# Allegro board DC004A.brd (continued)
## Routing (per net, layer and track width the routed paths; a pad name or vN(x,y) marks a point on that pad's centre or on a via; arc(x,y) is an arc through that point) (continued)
VBUS:
  vias: v1(32.95,36.48)
VBUSS: length 1.9
  BOTTOM w0.305: v1(31.05,39.98) 31.05,39.05 31.34,38.76 C173.1
VCCIN: length 2.3
  TOP w0.381: v1(66.02,137.01) 65.88,137.15 C104.2
  BOTTOM w0.305: v1(66.02,137.01) 65.92,137.11 U3.10
VDDD33: length 28.5
  TOP w0.254: U11.7 v1(76.22,58.61) ; U2.1 v1(12.15,124.12) ; U11.8 v1(76.2,57.96) ; U2.10 11.25,123.75 v1(11.68,123.32) ; U11.16 U11.1 77.62,62.5 v1(77.62,62.14) 77.61,62.13 U11.2
  TOP w0.305: U8.42 v1(64.76,62.35) ; v1(62.31,55.96) U8.31 ; U8.20 v1(56.8,56.1) ; U8.56 v1(59.31,67.09) ; U12.16 87.62,72.27 v1(87.62,73.15)
  TOP w0.356: U10.8 v1(44.69,35.44) ; U10.2 43.58,39.75 v1(43.59,39.75) 43.59,39.99 U10.1 ; U10.16 v1(49.23,40.47)
  TOP w0.508: v1(74.36,68.98) v1(74.36,67.84)
  BOTTOM w0.279: C190.1 v1(48.67,53.11)
  BOTTOM w0.305: v1(56.8,56.1) C186.1 ; C188.1 v1(62.31,55.96) ; C187.1 63.31,62.35 v1(64.76,62.35) ; C189.1 59.31,67.09 v1(59.31,67.09)
  BOTTOM w0.508: C180.1 76.95,73.12 v1(77.02,73.19) ; FB12.1 51.82,66.29 v1(52.2,66.67)
  vias: v1(6.68,125.64) v1(6.68,124.5) v1(6.68,123.35) v1(11.68,122.17) v1(14.48,127.25) v1(24.51,145.67) v1(24.51,144.65) v1(24.51,143.64) v1(24.51,142.75) v1(24.51,141.73) v1(25.27,143.76) v1(25.27,141.61) v1(25.78,145.03) v1(26.01,143) v1(26.16,141.61) v1(26.29,143.89) v1(42.04,120.78) v1(42.14,124.76) v1(42.65,125.26) v1(42.65,124.25) v1(42.8,121.28) v1(43.43,120.78) v1(50.55,70.61) v1(50.98,58.84) v1(51.31,69.85) v1(51.38,60.07) v1(66.88,53.78) v1(68.96,63.75) v1(68.96,61.47) v1(78.82,65.6) v1(107.95,68.83) v1(107.98,66.17) v1(107.98,64.52) v1(107.98,62.61) v1(110.24,62.23)
VDDL19: length 8.7
  TOP w0.305: U12.15 87.57,71.62 v1(85.86,71.62) ; U11.15 v1(81.75,61.86)
  BOTTOM w0.279: v1(47.52,39.24) 47.62,39.34 v1(49.23,39.34) 49.13,39.24 R132.1
  BOTTOM w0.508: v1(81.75,61.86) 81.78,61.89 C193.1 ; C195.1 v1(85.86,71.62)
  vias: v1(72.97,70.3) v1(73.05,69.52) v1(73.66,70.65) v1(73.77,69.86) v1(83.85,40.77) v1(84.71,41.53) v1(85.22,40.77) v1(85.34,39.37) v1(85.85,41.53) v1(86.36,39.62) v1(86.49,38.73) v1(86.74,41.53) v1(86.74,40.26) v1(87.5,41.53)
VINA: length 4.8
  TOP w0.279: BALUN1.1 31.93,123.44
VINB: length 4.8
  TOP w0.279: BALUN2.1 31.93,68.07
1P8V_USB: length 51.7
  TOP w0.305: U8.64 v1(55.3,66.99) ; v1(64.67,59.84) U8.37 ; v1(63.12,68.07) 62.81,67.76 U8.49 ; v1(53.8,59.84) U8.12
  L10_SIG-2 w0.508: 56.11,58.85 53.14,55.88 v1(44.07,55.88)
  BOTTOM w0.254: v1(55.3,66.99) 55.3,66.05 C181.1
  BOTTOM w0.279: 54.61,57.15 54.61,59.46 C182.1 54.05,59.59 v1(53.8,59.84) ; C183.1 v1(64.67,59.84) 65.03,59.48
  BOTTOM w0.305: v1(63.12,68.07) 62.81,67.76 C179.1
  BOTTOM w0.508: v1(44.07,55.88) 53.34,55.88 54.61,57.15 56.77,54.99 63.32,54.99 65.41,57.08 65.41,59.1 65.03,59.48
  vias: v1(62.74,68.58) v1(63.5,67.56)
3P3USB: length 16.9
  TOP w0.305: U8.9 53.95,61.34 53.94,61.36 53.51,61.36 52.65,60.5 v1(52.65,60.07)
  BOTTOM w0.254: v1(44.07,59.69) 46.07,59.69 47.11,60.73 50.47,60.73 51.71,61.98 53.72,61.98 54.36,61.34 53.95,61.34 53.91,61.38 53.31,61.38 C171.1
  BOTTOM w0.279: C171.1 53.26,61.24 53.16,61.14 53.16,60.99 53.15,60.97 53.15,60.57 v1(52.65,60.07)
  BOTTOM w0.508: C170.1 54.36,61.34
3P3V_RX: length 19.5
  BOTTOM w0.279: v1(139.06,58.93) 139.06,58.63 137.58,57.15 125.98,57.15 123.95,55.12 v1(121.28,55.12)
3P3VAUX: length 29.7
  TOP w0.279: v1(122.73,58.93) 121.78,58.93 121.61,59.09 U5.8
  L04_SIG-1 w0.165: J28.4 123.19,62.48 123.83,61.85 123.83,60.02 v1(122.73,58.93)
  BOTTOM w0.102: 128.52,70.87 138.43,70.87 J25.D32
  BOTTOM w0.279: J28.4 124.59,70.87 128.52,70.87
12P0V_RX:
  vias: v1(140.34,67.69) v1(140.34,65.15)
ADBUS0: length 6.3
  TOP w0.152: SJP3.3 50.93,55.75 53.02,57.84 53.4,57.84 53.4,57.84 53.78,57.84 53.79,57.84 U8.16
ADBUS1: length 5.2
  TOP w0.152: SJP4.3 52.58,55.88 53.71,57.02 U8.17
ADBUS2: length 3.8
  TOP w0.152: SJP5.3 54.23,54.74 55.8,56.31 U8.18
ADBUS3: length 3.3
  TOP w0.152: U8.19 56.3,54.14 SJP6.3
ADC_CLK: length 90.3
  L04_SIG-1 w0.14: 43.88,67.73 43.88,61.09 38.73,55.94 38.73,43.69 v1(38.86,43.56) 41.4,41.02 44.07,41.02 45.09,40 v1(53.34,40)
  L04_SIG-1 w0.152: v1(41.42,96.26) 43.57,96.26 44.98,94.84 44.98,89.18 45.34,88.82 45.34,79.38 43.88,77.92 43.88,67.73
  BOTTOM w0.127: v1(53.34,40) 51.63,41.72 40.83,41.72 38.99,43.56 v1(38.86,43.56)
ADC_SCSB: length 97.7
  L04_SIG-1 w0.089: 34.93,88.39 34.93,90.47 35.23,90.78 35.69,90.78 35.94,91.03 35.94,95.66 36.07,95.78 39.95,95.78 v1(40.43,96.26)
  L04_SIG-1 w0.14: v1(53.34,36.58) 51.94,36.58 51.35,37.17 38.9,37.17 35.46,40.61 35.46,62.13 35.71,62.38 35.71,76.34 35.17,76.88 35.17,83.19 34.29,84.07 34.29,87.76 34.93,88.39
  BOTTOM w0.127: v1(53.34,36.58) 53.34,35.18 52.32,34.16 40.01,34.16 v1(38.86,35.31)
ADC_SDI: length 98.4
  L04_SIG-1 w0.14: v1(53.34,38.86) 53.09,38.61 46.48,38.61 46.2,38.89 46.12,38.82 45.77,38.82 45.6,38.99 39.88,38.99 36.37,42.49 36.37,76.58
  L04_SIG-1 w0.152: 36.37,76.58 35.81,77.14 35.81,86.66 36.22,87.07 42.29,87.07 44.2,88.98 44.2,95 43.46,95.73 40.9,95.73 v1(40.43,95.26)
  BOTTOM w0.127: v1(53.34,38.86) 52.32,38.86 50.04,41.15 48.9,41.15 48.51,40.77 v1(38.86,40.77)
ADC_SDO: length 96.2
  L04_SIG-1 w0.089: v1(41.42,95.26) 41.42,94.03 41.22,93.83 37.13,93.83 36.91,93.6 36.91,88.85 36.45,88.39
  L04_SIG-1 w0.14: v1(53.34,37.72) 40.13,37.72 36.02,41.83 36.02,62.24 36.03,62.25 36.03,76.47 35.49,77.01 35.49,87.43 36.45,88.39
  BOTTOM w0.127: v1(38.86,38.1) 38.86,37.47 41.78,34.54 51.94,34.54 52.45,35.05 52.45,36.83 v1(53.34,37.72)
BDBUS0: length 2.9
  TOP w0.279: R112.1 59.82,55.79 59.79,55.82 59.79,56.25 59.82,56.28 59.82,57 U8.26
BDBUS1: length 6.4
  TOP w0.279: v1(60.31,56.03) U8.27 ; U7.2 v1(63.13,52.83)
  L10_SIG-2 w0.165: v1(60.31,56.03) 60.31,55.65 v1(63.13,52.83)
BDBUS2: length 3
  TOP w0.279: U8.28 60.81,56.27 60.83,56.25 60.83,55.82 60.81,55.8 60.81,54.26 R113.1
BDBUS3: length 5.2
  TOP w0.279: U8.29 61.31,55.41 62.93,53.78 U7.1
CALTRG: length 33.9
  TOP w0.152: v1(36.2,104.65) 36.2,103.76 36.43,103.53 U1.A9
  L04_SIG-1 w0.14: 39.12,124.21 39.37,124.21 40.77,122.81 44.32,122.81 44.7,122.43 44.7,109.86 41.15,106.3 37.56,106.3 36.92,105.66
  L04_SIG-1 w0.152: 36.92,105.66 36.2,104.93 v1(36.2,104.65)
  BOTTOM w0.254: 37.47,124.21 39.12,124.21
CDBUS0: length 4.8
  TOP w0.279: R118.1 66.78,60.34 64.91,60.34 64.89,60.36 64.45,60.36 64.43,60.34 U8.38
CDBUS1: length 4.5
  TOP w0.279: R119.1 67.43,60.84 U8.39
CDBUS2: length 6.9
  TOP w0.279: R120.1 69.34,62.1 68.58,62.1 R115.2 67.82,61.34 U8.40
CDBUS3: length 7.8
  TOP w0.254: R114.2 67.94,62.99 68.33,62.61 R121.1
  TOP w0.279: 67.94,62.99 66.8,61.85 64.99,61.85 64.97,61.82 64.54,61.82 64.52,61.85 U8.41
CE: length 5.3
  BOTTOM w0.279: U3.1 66.97,141.61 R46.1 67.79,142.44 68.81,142.44 JP5.2
CLK+: length 3.3
  TOP w0.279: C49.1 21.72,96.27 20.7,96.27 20.12,96.85 arc(19.92,96.98) 19.68,97.03 T2.1
CLK-: length 3.3
  TOP w0.279: T2.3 19.68,94.49 arc(19.92,94.53) 20.12,94.67 R43.1 21.72,95.25 C52.1
CLK-IN: length 5.7
  BOTTOM w0.279: R70.2 R72.1 R67.1 T1.6 R69.1
CLK_+: length 5.6
  TOP w0.279: U1.G1 23.17,96.26 arc(23,96.29) v1(22.86,96.39)
CLK_-: length 5.6
  TOP w0.279: U1.H1 23.17,95.26 arc(23,95.23) v1(22.86,95.13)
CLKIN0: length 27.9
  BOTTOM w0.279: J38.1 84.43,124.91 arc(85.14,124.77) 85.73,124.37 85.96,124.15 arc(86.1,124.06) 86.26,124.02 R187.1 87.81,124.02 R186.1
CLKIN0_N: length 3.9
  BOTTOM w0.254: C24.2 90.05,124.53 arc(90.26,124.49) 90.45,124.37 arc(91.09,123.94) 91.84,123.79 U4.38
CLKIN0_P: length 3.8
  BOTTOM w0.254: C20.2 90.28,123.77 arc(90.38,123.75) 90.46,123.69 90.58,123.57 arc(90.89,123.37) 91.24,123.3 92.96,123.3 92.97,123.29 U4.37
CLKIN1: length 0.7
  BOTTOM w0.279: R186.2 C20.1
CLKIN1_N: length 4
  BOTTOM w0.254: C136.2 90.52,122.42 C137.2 arc(90.77,122.36) 90.97,122.23 91.04,122.16 arc(91.18,122.06) 91.35,122.03 92.23,122.03 arc(92.38,122.06) 92.51,122.14 arc(92.66,122.25) 92.85,122.29 U4.35
CLKIN1_P: length 4
  BOTTOM w0.254: U4.34 93.17,121.79 arc(92.99,121.75) 92.84,121.65 92.76,121.57 arc(92.48,121.38) 92.14,121.32 91.18,121.32 arc(90.9,121.37) 90.66,121.53 arc(90.52,121.63) 90.35,121.66 C134.2
CLKINN: length 4.4
  BOTTOM w0.279: C136.1 87.43,122.42 R73.2 86.8,123.05 arc(86.57,123.21) 86.29,123.26 T1.3
CLKINP: length 5.1
  BOTTOM w0.279: C134.1 R68.1 87.53,121.66 R73.1 86.84,120.97 arc(86.56,120.79) 86.23,120.72 T1.1 R69.2
CLKLA_0N: length 5.1
  BOTTOM w0.152: U4.63 101.27,130.11 101.16,130.22 101.16,133.53 R90.1 101.35,134.39 R127.1
CLKLA_0P: length 5.1
  BOTTOM w0.152: U4.62 100.77,130.14 100.88,130.25 100.88,133.53 R89.1 100.69,134.39 R126.1
CLKM: length 105.3
  BOTTOM w0.254: C135.2 104.3,116.41 104.3,114.87 arc(103.45,112.81) 101.39,111.96 37.32,111.96 arc(36.49,112.13) 35.79,112.6 34.93,113.46 arc(34.46,113.76) 33.91,113.87 30.91,113.87 arc(30.68,113.91) 30.48,114.05 30.47,114.06 arc(30.41,114.11) 30.35,114.16 arc(30.14,114.25) 29.93,114.28 29.81,114.28 arc(29.48,114.22) 29.19,114.02 arc(29.02,113.91) 28.83,113.86 arc(27.53,113.55) 26.43,112.79 25.78,112.14 arc(25.61,112.02) 25.41,111.98 arc(25.2,111.9) 25.02,111.76 arc(24.93,111.62) 24.89,111.45 arc(24.85,111.27) 24.75,111.11 24.21,110.57 arc(23.91,110.37) 23.56,110.3 arc(23.15,110.13) 22.99,109.73 arc(22.96,109.61) 22.9,109.51 22.7,109.32 arc(22.54,109.07) 22.48,108.78 22.48,108.42 arc(22.46,108.18) 22.4,107.93 arc(22.2,107.11) 22.13,106.26 arc(22.15,106.19) 22.15,106.13 22.15,105.79 arc(22.11,105.54) 22.01,105.32 21.97,105.28 arc(21.81,105.03) 21.75,104.73 arc(21.78,104.4) 21.89,104.09 21.89,104.09 arc(22.08,103.8) 22.15,103.46 22.15,102.98 arc(22.11,102.76) 21.98,102.57 21.98,102.57 arc(21.8,102.2) 21.74,101.78 arc(21.79,101.51) 21.95,101.28 arc(22.1,101.05) 22.15,100.79 22.15,100.46 arc(22.65,99.24) 23.88,98.73 24.77,98.73 arc(25.34,98.49) 25.58,97.92 25.58,96.65 arc(25.42,96.27) 25.04,96.11 24.72,96.11 arc(24.62,96.13) 24.54,96.19 24.41,96.32 arc(24.33,96.37) 24.23,96.39 C48.1
CLKP: length 105.2
  BOTTOM w0.254: C133.2 105.01,116.41 105.01,114.87 arc(103.95,112.31) 101.39,111.25 37.32,111.25 arc(36.22,111.47) 35.29,112.09 34.44,112.94 arc(34.19,113.1) 33.91,113.16 29.03,113.16 arc(28.95,113.15) 28.87,113.15 arc(27.82,112.9) 26.93,112.28 26.02,111.37 24.34,109.69 arc(23.24,108.06) 22.86,106.13 22.86,100.46 arc(23.16,99.74) 23.88,99.44 24.77,99.44 arc(25.84,98.99) 26.29,97.92 26.29,96.65 arc(25.92,95.77) 25.04,95.4 24.72,95.4 arc(24.62,95.38) 24.54,95.33 24.41,95.2 arc(24.33,95.14) 24.23,95.12 C53.1
CP1: length 38.7
  L04_SIG-1 w0.14: v1(94.21,118.43) 89.41,118.43 85.55,122.3 85.55,128.87 77.07,137.36 v1(77.07,141.29)
  BOTTOM w0.279: v1(77.07,141.29) 77.07,144.9 C130.1 ; v1(94.21,118.43) 94.27,118.49 U4.32
CP2: length 4.9
  BOTTOM w0.127: 90.11,128.98 C131.1 ; U4.46 93.44,127.79
  BOTTOM w0.279: 93.44,127.79 92.38,127.79 91.19,128.98 90.11,128.98 ; C132.1 C131.1
CPOUT: length 17.7
  TOP w0.279: v1(64.14,134.37) 67.06,134.37 68.07,135.38 68.07,139.83 67.31,140.59 67.31,144.06 v1(67.69,144.44)
  BOTTOM w0.127: v1(64.14,134.37) 64.11,134.39 64.11,135.26 63.8,135.56
  BOTTOM w0.203: 63.8,135.56 U3.12
  BOTTOM w0.254: C120.1 C119.1 v1(67.69,144.44)
DA0+: length 1.5
  TOP w0.254: C5.1 41.77,98.11 arc(41.58,98.15) U1.E14
DA0-: length 1.5
  TOP w0.254: C6.1 41.77,97.4 arc(41.58,97.37) U1.F14
DA0_M: length 100.6
  TOP w0.254: C6.2 43.97,97.4 115.67,97.4 arc(116.12,97.31) 116.51,97.05 116.68,96.88 arc(117.39,96.41) 118.23,96.24 124.08,96.24 v1(124.12,96.2)
  BOTTOM w0.254: J25.A11 142.58,97.88 arc(142.2,97.62) 141.76,97.54 128.55,97.54 arc(128.46,97.56) 128.37,97.61 128.24,97.74 arc(128.16,97.8) 128.06,97.82 127.66,97.82 arc(127.38,97.76) 127.13,97.59 126.37,96.83 arc(125.7,96.38) 124.91,96.23 124.14,96.23 v1(124.12,96.2)
DA0_P: length 100.6
  TOP w0.254: C5.2 115.67,98.11 arc(116.4,97.97) 117.01,97.56 117.18,97.39 arc(117.67,97.06) 118.23,96.95 124.1,96.95 v1(124.12,96.96)
  BOTTOM w0.254: v1(124.12,96.96) 124.14,96.94 124.91,96.94 arc(125.43,97.04) 125.87,97.33 126.63,98.1 arc(127.1,98.42) 127.66,98.53 128.06,98.53 arc(128.16,98.55) 128.24,98.6 128.37,98.73 arc(128.46,98.79) 128.55,98.81 141.84,98.81 arc(142.21,98.88) 142.52,99.09 J25.A10
DA1+: length 1.5
  TOP w0.254: C7.1 41.77,100.11 arc(41.58,100.15) U1.C14
DA1-: length 1.5
  TOP w0.254: C8.1 41.77,99.4 arc(41.58,99.37) U1.D14
DA1_M: length 99.6
  TOP w0.254: v1(118.56,100.94) 118.53,100.94 118.11,100.52 arc(117.61,100.19) 117.03,100.08 46.32,100.08 arc(46.02,100.02) 45.77,99.85 arc(45.28,99.52) 44.7,99.4 43.97,99.4 C8.2
  BOTTOM w0.254: v1(118.56,100.94) 118.56,100.98 120.43,102.85 arc(121.19,103.36) 122.08,103.53 122.65,103.53 arc(122.83,103.5) 122.98,103.4 123.46,102.92 arc(123.6,102.83) 123.76,102.79 123.88,102.79 arc(124.04,102.83) 124.18,102.92 124.67,103.41 arc(124.81,103.5) 124.97,103.53 127.02,103.53 arc(127.38,103.46) 127.69,103.25 128.09,102.85 arc(128.36,102.68) 128.67,102.61 129.02,102.61 138.99,102.62 139.88,102.62 arc(140.2,102.75) 140.34,103.07 J25.C7
DA1_P: length 99.6
  TOP w0.254: C7.2 44.7,100.11 arc(45.01,100.17) 45.27,100.35 45.27,100.35 arc(45.75,100.67) 46.32,100.79 112.8,100.79 arc(113.02,100.83) 113.2,100.95 113.62,101.37 arc(113.84,101.52) 114.1,101.57 114.29,101.57 arc(114.56,101.52) 114.78,101.37 115.09,101.06 115.22,100.93 arc(115.38,100.83) 115.57,100.79 117.03,100.79 arc(117.34,100.85) 117.6,101.03 118.02,101.45 v1(118.02,101.48)
  BOTTOM w0.254: J25.C6 140.34,104.7 arc(140.2,105.02) 139.88,105.16 138.99,105.16 129.02,105.16 128.67,105.16 arc(128.35,105.1) 128.08,104.92 127.69,104.52 arc(127.38,104.32) 127.02,104.24 122.08,104.24 arc(120.92,104.01) 119.93,103.35 118.06,101.48 v1(118.02,101.48)
DA2+: length 1.5
  TOP w0.254: C9.1 39.57,102.61 arc(39.53,102.42) U1.A12
DA2-: length 1.5
  TOP w0.254: C10.1 40.28,102.61 arc(40.32,102.42) U1.A13
DA2_M: length 108.2
  TOP w0.254: C10.2 40.28,104.37 arc(40.6,105.15) 41.38,105.47 42.22,105.47 arc(42.41,105.43) 42.57,105.32 42.7,105.19 42.84,105.06 arc(43.02,104.93) 43.23,104.89 43.4,104.89 arc(43.64,104.94) 43.85,105.08 43.96,105.19 44.09,105.32 arc(44.25,105.43) 44.45,105.47 45.17,105.47 arc(45.37,105.43) 45.53,105.32 45.66,105.19 45.8,105.06 arc(46.01,104.91) 46.27,104.86 arc(46.56,104.92) 46.81,105.08 46.92,105.19 47.05,105.32 arc(47.21,105.43) 47.41,105.47 48.24,105.47 arc(48.43,105.43) 48.6,105.32 48.72,105.19 48.86,105.06 arc(49.04,104.93) 49.26,104.89 49.42,104.89 arc(49.66,104.94) 49.87,105.08 49.99,105.19 50.11,105.32 arc(50.28,105.43) 50.47,105.47 108.75,105.47 arc(109.98,105.71) 111.02,106.41 arc(111.5,106.73) 112.06,106.84 136.2,106.84 arc(136.67,106.64) 136.86,106.17 136.86,104.28 arc(137.27,103.3) 138.26,102.89 140.97,102.89 arc(141.1,102.86) 141.21,102.79 arc(141.36,102.69) 141.53,102.66 142.28,102.66 arc(142.7,102.83) v1(142.88,103.25)
DA2_P: length 108.2
  TOP w0.254: C9.2 39.57,104.37 arc(40.1,105.65) 41.38,106.18 108.75,106.18 arc(109.71,106.37) 110.52,106.91 arc(111.22,107.38) 112.05,107.55 136.2,107.55 arc(137.17,107.15) 137.57,106.17 137.57,104.28 arc(137.77,103.8) 138.26,103.6 140.72,103.6 arc(140.95,103.65) 141.15,103.78 141.16,103.79 arc(141.29,103.87) 141.45,103.91 142.26,103.91 arc(142.69,104.09) v1(142.88,104.52)
DA3+: length 1.5
  TOP w0.254: C11.1 37.57,102.61 arc(37.53,102.42) U1.A10
DA3-: length 1.5
  TOP w0.254: C12.1 38.28,102.61 arc(38.32,102.42) U1.A11
DA3_M: length 108.3
  TOP w0.254: C12.2 38.28,105.03 arc(38.34,105.32) 38.51,105.57 39.73,106.79 arc(41.49,107.97) 43.56,108.38 44.32,108.38 arc(44.63,108.32) 44.89,108.15 44.97,108.06 arc(45.13,107.96) 45.31,107.92 45.82,107.92 arc(46.03,107.96) 46.21,108.08 46.34,108.21 arc(46.5,108.32) 46.7,108.36 47.17,108.36 arc(47.36,108.32) 47.53,108.21 47.65,108.09 47.79,107.95 arc(47.94,107.85) 48.13,107.81 48.41,107.81 arc(48.62,107.85) 48.8,107.97 48.92,108.08 49.04,108.21 arc(49.21,108.32) 49.4,108.36 50.96,108.36 arc(51.24,108.31) 51.47,108.15 51.48,108.14 arc(51.79,107.93) 52.16,107.86 arc(52.5,107.93) 52.79,108.12 arc(53.03,108.29) 53.33,108.35 53.74,108.35 arc(53.94,108.3) 54.12,108.19 54.12,108.18 arc(54.38,108.01) 54.68,107.95 arc(54.85,107.98) 54.99,108.08 arc(55.31,108.29) 55.68,108.36 106.65,108.36 v1(106.68,108.34)
  BOTTOM w0.254: v1(106.68,108.34) 106.7,108.36 113.79,108.36 arc(114.45,108.49) 115.01,108.86 arc(115.43,109.15) 115.93,109.25 128.06,109.25 arc(128.16,109.23) 128.24,109.17 128.37,109.04 arc(128.46,108.99) 128.55,108.97 141.76,108.97 arc(142.2,108.88) 142.58,108.62 J25.A3
DA3_P: length 108.2
  TOP w0.254: v1(106.68,109.1) 43.95,109.1 43.95,109.09 43.56,109.09 arc(41.21,108.63) 39.22,107.3 38,106.07 arc(37.68,105.59) 37.57,105.03 C11.2
  BOTTOM w0.254: v1(106.68,109.1) 106.7,109.07 113.79,109.07 arc(114.18,109.15) 114.5,109.37 arc(115.16,109.8) 115.93,109.96 128.06,109.96 arc(128.16,109.98) 128.24,110.03 128.37,110.16 arc(128.46,110.22) 128.55,110.24 141.76,110.24 arc(142.2,110.15) 142.58,109.89 J25.A2
DA4+: length 1.5
  BOTTOM w0.254: C13.1 40.77,98.11 arc(40.58,98.15) v1(40.43,98.26)
DA4-: length 1.5
  BOTTOM w0.254: C15.1 40.77,97.4 arc(40.58,97.36) v1(40.43,97.26)
DA4_M: length 106.5
  L10_SIG-2 w0.16: v1(107.38,94.33) 107.45,94.33 107.98,93.8 arc(108.65,93.35) 109.45,93.19 115.79,93.19 arc(117.03,92.94) 118.08,92.24 arc(119.58,91.24) 121.35,90.89 136.59,90.89 arc(137.89,91.14) 138.98,91.88 139.03,91.92 arc(139.93,92.52) 140.99,92.73 141.1,92.73 arc(141.2,92.72) 141.3,92.69 arc(141.36,92.65) 141.41,92.61 arc(141.59,92.49) 141.79,92.45 144.95,92.45 arc(145.28,92.59) 145.41,92.92 v1(145.41,93.09)
  BOTTOM w0.254: v1(107.38,94.33) 107.38,94.37 106.32,95.43 arc(105.58,95.95) 104.71,96.19 arc(104.58,96.2) 104.46,96.2 104.01,96.2 arc(103.94,96.2) 103.87,96.18 arc(103.75,96.13) 103.65,96.05 103.53,95.93 103.23,95.63 arc(103,95.48) 102.72,95.42 102.3,95.42 arc(102.03,95.48) 101.79,95.63 101.24,96.18 arc(100.95,96.38) 100.61,96.44 47.35,96.44 arc(46.75,96.56) 46.23,96.91 45.96,97.18 arc(45.71,97.34) 45.42,97.4 C15.2
DA4_P: length 106.5
  L10_SIG-2 w0.16: v1(145.41,94.36) 145.41,94.19 arc(145.28,93.86) 144.95,93.73 141.7,93.73 arc(141.55,93.7) 141.43,93.61 141.31,93.5 arc(141.21,93.43) 141.09,93.41 140.99,93.41 arc(139.67,93.14) 138.55,92.4 138.51,92.35 arc(137.63,91.76) 136.59,91.56 121.35,91.56 arc(119.84,91.86) 118.55,92.72 arc(117.29,93.56) 115.79,93.86 113.71,93.86 arc(113.52,93.9) 113.37,94 113.21,94.15 113.21,94.16 arc(113.1,94.23) 112.98,94.25 112.61,94.25 arc(112.47,94.23) 112.35,94.15 112.17,93.96 arc(112.05,93.89) 111.92,93.86 111.45,93.86 arc(111.26,93.9) 111.11,94 110.96,94.15 110.95,94.16 arc(110.86,94.22) 110.75,94.24 110.32,94.24 arc(110.2,94.22) 110.09,94.15 109.91,93.96 arc(109.8,93.89) 109.66,93.86 109.45,93.86 arc(108.91,93.97) 108.46,94.27 107.92,94.81 v1(107.92,94.87)
  BOTTOM w0.254: v1(107.92,94.87) 107.88,94.87 106.82,95.94 arc(105.88,96.59) 104.78,96.9 104.64,96.9 arc(104.45,96.94) 104.3,97.04 arc(104.09,97.13) 103.88,97.16 47.35,97.16 arc(47.02,97.22) 46.74,97.41 46.46,97.68 46.46,97.68 arc(45.99,98) 45.42,98.11 C13.2
DA5+: length 1.5
  BOTTOM w0.254: C16.1 40.77,100.11 arc(40.58,100.15) v1(40.43,100.26)
DA5-: length 1.5
  BOTTOM w0.254: C18.1 40.77,99.4 arc(40.58,99.36) v1(40.43,99.26)
DA5_M: length 105.8
  L10_SIG-2 w0.16: v1(121.92,99.6) 121.97,99.65 125.35,99.65 arc(126.37,99.45) 127.23,98.87 127.7,98.4 arc(128.37,97.96) 129.15,97.8 134.43,97.8 arc(134.66,97.75) 134.86,97.62 arc(134.99,97.53) 135.14,97.5 136.31,97.5 arc(137.15,97.67) 137.86,98.14 arc(138.59,98.63) 139.45,98.81 143.88,98.81 arc(144.71,98.64) v1(145.41,98.17)
  BOTTOM w0.254: v1(121.92,99.6) 121.9,99.63 121.41,99.63 arc(121.06,99.56) 120.77,99.36 120.21,98.8 arc(119.54,98.36) 118.75,98.2 110.09,98.2 arc(108.21,98.57) 106.62,99.64 106.43,99.83 arc(105.23,100.63) 103.81,100.91 45.91,100.91 arc(45.32,100.79) 44.83,100.46 44.18,99.82 arc(43.72,99.51) 43.18,99.4 C18.2
DA5_P: length 105.8
  L10_SIG-2 w0.16: v1(121.92,100.37) 121.97,100.32 125.35,100.32 arc(126.62,100.07) 127.7,99.35 128.18,98.87 arc(128.62,98.58) 129.15,98.47 134.44,98.47 arc(134.69,98.52) 134.89,98.66 arc(135.06,98.77) 135.25,98.8 136.4,98.8 arc(136.89,98.9) 137.31,99.18 arc(138.31,99.85) 139.5,100.09 143.85,100.09 arc(144.7,99.92) v1(145.41,99.44)
  BOTTOM w0.254: C16.2 43.18,100.11 arc(43.45,100.17) 43.68,100.32 44.32,100.97 arc(45.05,101.45) 45.91,101.62 103.81,101.62 arc(105.5,101.29) 106.93,100.33 107.12,100.14 arc(108.48,99.23) 110.09,98.91 118.75,98.91 arc(119.27,99.01) 119.71,99.31 120.27,99.87 arc(120.79,100.22) 121.41,100.34 121.9,100.34 v1(121.92,100.37)
DA6+: length 1.5
  BOTTOM w0.254: C19.1 39.57,101.4 v1(39.42,101.26)
DA6-: length 1.5
  BOTTOM w0.254: C21.1 40.28,101.4 v1(40.43,101.26)
DA6_M: length 106.5
  L10_SIG-2 w0.16: v1(110.87,103.16) 110.92,103.2 113.13,103.2 arc(113.91,103.36) 114.57,103.8 114.81,104.04 arc(115.44,104.47) 116.19,104.61 128.98,104.61 arc(129.65,104.48) 130.22,104.1 131.87,102.46 arc(132.78,101.84) 133.87,101.63 134.77,101.63 arc(134.99,101.58) 135.18,101.46 arc(135.33,101.36) 135.51,101.32 140.28,101.32 arc(140.94,101.19) 141.49,100.82 v1(141.6,100.71)
  BOTTOM w0.254: v1(110.87,103.16) 110.85,103.18 108.47,103.18 arc(106.95,103.49) 105.65,104.35 arc(104.41,105.18) 102.95,105.47 50.34,105.47 arc(50.15,105.43) 49.98,105.32 49.85,105.2 49.74,105.08 arc(49.56,104.96) 49.35,104.92 49.06,104.92 arc(48.88,104.96) 48.73,105.06 48.59,105.2 48.46,105.32 arc(48.3,105.43) 48.11,105.47 47.45,105.47 arc(47.25,105.43) 47.09,105.32 46.96,105.2 46.85,105.08 arc(46.62,104.93) 46.36,104.88 46.28,104.88 arc(46.04,104.92) 45.84,105.06 45.7,105.2 45.57,105.32 arc(45.41,105.43) 45.22,105.47 44.57,105.47 arc(44.38,105.43) 44.21,105.32 44.09,105.2 43.97,105.08 arc(43.79,104.96) 43.58,104.92 43.3,104.92 arc(43.11,104.96) 42.96,105.06 42.82,105.2 42.69,105.32 arc(42.53,105.43) 42.34,105.47 41.36,105.47 arc(40.6,105.16) 40.28,104.39 C21.2
DA6_P: length 106.5
  L10_SIG-2 w0.16: v1(141.6,101.98) 141.49,102.09 arc(140.94,102.46) 140.28,102.59 135.47,102.59 arc(135.24,102.55) 135.06,102.42 135.05,102.42 arc(134.92,102.33) 134.75,102.3 133.87,102.3 arc(133.04,102.46) 132.34,102.93 130.7,104.57 arc(129.91,105.1) 128.98,105.29 116.19,105.29 arc(115.19,105.09) 114.34,104.52 114.09,104.27 arc(113.65,103.98) 113.13,103.88 110.92,103.88 v1(110.87,103.92)
  BOTTOM w0.254: C19.2 39.57,104.39 arc(40.09,105.66) 41.36,106.18 102.95,106.18 arc(104.69,105.84) 106.15,104.86 arc(107.22,104.15) 108.47,103.9 110.85,103.9 v1(110.87,103.92)
DA7+: length 1.5
  BOTTOM w0.254: v1(37.42,101.26) 37.57,101.4 C22.1
DA7-: length 1.5
  BOTTOM w0.254: v1(38.43,101.26) 38.28,101.4 C23.1
DA7_M: length 112.2
  L10_SIG-2 w0.16: v1(108.88,111.45) 108.93,111.5 109.8,111.5 arc(110.66,111.33) 111.39,110.84 113.28,108.95 arc(114.37,108.22) 115.66,107.96 135.83,107.96 arc(136.4,108.07) 136.88,108.4 137.05,108.56 arc(137.5,108.86) 138.03,108.97 139.43,108.97 arc(139.82,108.81) 139.98,108.42 139.98,107.27 arc(140.32,106.46) 141.13,106.12 141.27,106.12 arc(141.51,106.03) v1(141.6,105.79)
  BOTTOM w0.254: v1(108.88,111.45) 108.86,111.48 107.19,111.48 arc(105.74,111.19) 104.52,110.37 104.12,109.97 arc(103.41,109.5) 102.58,109.34 58.77,109.34 arc(58.45,109.27) 58.17,109.09 58.04,108.96 arc(57.77,108.78) 57.45,108.71 56.49,108.71 arc(56.16,108.78) 55.88,108.97 arc(55.47,109.24) 54.99,109.34 52.83,109.34 arc(52.48,109.27) 52.18,109.07 52.11,108.99 arc(51.8,108.78) 51.44,108.71 ; 51.44,108.71 51.43,108.71 ; 51.44,108.71 51.43,108.71 ; 51.43,108.71 50.42,108.71 arc(49.95,108.81) 49.55,109.07 49.53,109.09 arc(49.26,109.27) 48.94,109.34 47.04,109.34 arc(46.63,109.25) 46.28,109.02 46.1,108.84 arc(45.93,108.73) 45.73,108.69 45.2,108.69 arc(45,108.73) 44.83,108.84 44.8,108.87 arc(44.29,109.22) 43.68,109.34 43.68,109.34 arc(42.38,109.08) 41.27,108.34 39.7,106.77 arc(38.65,105.19) C23.2
DA7_P: length 112.2
  L10_SIG-2 w0.16: v1(141.6,107.06) 141.6,106.96 arc(141.55,106.84) 141.43,106.79 141.13,106.79 arc(140.79,106.93) 140.65,107.27 140.65,108.42 arc(140.29,109.28) 139.43,109.64 138.03,109.64 arc(137.24,109.48) 136.57,109.04 136.41,108.87 arc(136.14,108.69) 135.83,108.63 115.66,108.63 arc(114.63,108.84) 113.76,109.42 111.87,111.31 arc(110.92,111.94) 109.8,112.17 108.93,112.17 v1(108.88,112.21)
  BOTTOM w0.254: v1(108.88,112.21) 108.86,112.19 107.19,112.19 arc(105.47,111.84) 104.01,110.87 103.62,110.48 arc(103.14,110.16) 102.58,110.05 43.68,110.05 arc(42.1,109.73) 40.77,108.84 39.2,107.27 arc(37.99,105.47) C22.2
DB0+: length 1.5
  TOP w0.254: C25.1 41.77,93.4 arc(41.58,93.37) U1.K14
DB0-: length 1.5
  TOP w0.254: C26.1 41.77,94.11 arc(41.58,94.15) U1.J14
DB0_M: length 100.9
  TOP w0.254: C26.2 44.93,94.11 arc(45.64,93.97) 46.25,93.57 46.71,93.11 arc(47.09,92.85) 47.55,92.76 116.92,92.76 arc(118.01,92.54) 118.94,91.92 arc(119.8,91.35) 120.82,91.15 131.38,91.15 arc(134.66,91.8) 137.44,93.66 139.99,96.21 arc(140.45,96.51) 140.99,96.62 141.33,96.62 arc(141.52,96.7) v1(141.6,96.9)
DB0_P: length 100.9
  TOP w0.254: C25.2 44.93,93.4 arc(45.37,93.31) 45.75,93.07 46.2,92.61 arc(46.82,92.2) 47.55,92.05 116.92,92.05 arc(117.74,91.89) 118.44,91.42 arc(119.53,90.69) 120.82,90.44 131.38,90.44 arc(134.93,91.14) 137.94,93.15 140.5,95.71 arc(140.72,95.86) 140.99,95.91 141.33,95.91 arc(141.52,95.83) v1(141.6,95.63)
DB1+: length 1.5
  TOP w0.254: C27.1 41.77,91.4 arc(41.58,91.37) U1.M14
DB1-: length 1.5
  TOP w0.254: C28.1 41.77,92.11 arc(41.58,92.15) U1.L14
DB1_M: length 103.1
  TOP w0.254: v1(116.96,88.7) 116.95,88.68 49.83,88.68 arc(48.48,88.94) 47.34,89.71 45.35,91.7 arc(44.89,92.01) 44.35,92.11 C28.2
  BOTTOM w0.254: J25.A14 142.58,94.65 arc(142.2,94.91) 141.76,95 128.55,95 arc(128.46,94.98) 128.37,94.92 128.24,94.79 arc(128.16,94.74) 128.06,94.72 127.52,94.72 arc(125.76,94.37) 124.27,93.37 120.07,89.17 arc(119.52,88.81) 118.87,88.68 116.98,88.68 v1(116.96,88.7)
DB1_P: length 103.1
  TOP w0.254: v1(116.96,87.94) 116.9,87.96 49.83,87.96 arc(48.21,88.29) 46.84,89.2 44.84,91.2 arc(44.62,91.35) 44.35,91.4 C27.2
  BOTTOM w0.254: J25.A15 142.52,93.45 arc(142.21,93.65) 141.84,93.73 128.55,93.73 arc(128.46,93.75) 128.37,93.8 128.24,93.93 arc(128.16,93.99) 128.06,94.01 127.52,94.01 arc(126.03,93.71) 124.77,92.87 120.58,88.67 arc(119.79,88.15) 118.87,87.96 116.98,87.96 v1(116.96,87.94)
DB2+: length 1.5
  TOP w0.254: C29.1 39.57,88.91 arc(39.53,89.1) U1.P12
DB2-: length 1.5
  TOP w0.254: C30.1 40.28,88.91 arc(40.32,89.1) U1.P13
DB2_M: length 105.8
  TOP w0.254: v1(119.17,85.54) 118.61,85.54 118.58,85.51 53.17,85.51 arc(52.94,85.56) 52.74,85.69 52.7,85.73 arc(52.26,86.03) 51.73,86.13 51.4,86.13 arc(50.79,86.01) 50.28,85.67 50.24,85.63 arc(50.11,85.54) 49.96,85.51 49.15,85.51 arc(48.88,85.56) 48.65,85.72 48.48,85.89 arc(48.24,86.04) 47.97,86.1 arc(47.65,86.04) 47.37,85.85 47.15,85.63 arc(47.02,85.54) 46.86,85.51 46.21,85.51 arc(45.72,85.61) 45.3,85.89 arc(44.95,86.12) 44.54,86.2 arc(44.19,86.13) 43.9,85.93 43.82,85.85 arc(43.44,85.6) 42.99,85.51 41.83,85.51 arc(41.39,85.6) 41.02,85.85 40.69,86.17 arc(40.39,86.63) C30.2
  BOTTOM w0.254: J25.B16 141.25,91.47 arc(140.94,91.26) 140.57,91.19 128.3,91.19 arc(128.2,91.17) 128.12,91.11 127.99,90.98 arc(127.91,90.93) 127.81,90.91 126.72,90.91 arc(126.12,90.79) 125.62,90.45 121.21,86.04 arc(120.62,85.65) 119.93,85.51 119.2,85.51 v1(119.17,85.54)
DB2_P: length 105.8
  TOP w0.254: v1(119.17,84.77) 118.61,84.77 118.58,84.8 41.83,84.8 arc(41.12,84.94) 40.51,85.34 40.19,85.67 arc(39.73,86.35) C29.2
  BOTTOM w0.254: v1(119.17,84.77) 119.2,84.8 119.93,84.8 arc(120.89,84.99) 121.71,85.54 126.12,89.95 arc(126.4,90.13) 126.72,90.2 127.81,90.2 arc(127.91,90.18) 127.99,90.12 128.12,89.99 arc(128.2,89.94) 128.3,89.92 140.49,89.92 arc(140.93,90) 141.31,90.26 J25.B17
DB3+: length 1.5
  TOP w0.254: C31.1 37.57,88.91 arc(37.53,89.1) U1.P10
DB3-: length 1.5
  TOP w0.254: C32.1 38.28,88.91 arc(38.32,89.1) U1.P11
DB3_M: length 111.1
  TOP w0.254: v1(115.71,81.37) 115.69,81.34 50.63,81.34 arc(50.44,81.38) 50.27,81.49 50.15,81.62 50.01,81.75 arc(49.85,81.86) 49.67,81.89 49.39,81.89 arc(49.18,81.85) 49,81.73 48.88,81.62 48.76,81.49 arc(48.59,81.38) 48.4,81.34 48.09,81.34 arc(47.9,81.38) 47.73,81.49 47.61,81.62 47.47,81.75 arc(47.32,81.86) 47.13,81.89 46.85,81.89 arc(46.64,81.85) 46.46,81.73 46.34,81.62 46.22,81.49 arc(46.05,81.38) 45.86,81.34 43.61,81.34 arc(43.26,81.41) 42.97,81.6 38.89,85.69 arc(38.44,86.36) C32.2
  BOTTOM w0.254: v1(115.71,81.37) 115.74,81.34 117.76,81.34 arc(119.65,81.72) 121.26,82.79 126.41,87.93 arc(126.88,88.25) 127.45,88.37 128.06,88.37 arc(128.16,88.39) 128.24,88.44 128.37,88.57 arc(128.46,88.63) 128.55,88.65 141.84,88.65 arc(142.21,88.72) 142.52,88.93 J25.A18
DB3_P: length 111.5
  TOP w0.254: v1(115.71,80.6) 115.69,80.63 43.61,80.63 arc(42.99,80.75) 42.47,81.1 38.39,85.18 arc(37.78,86.09) C31.2
  BOTTOM w0.254: v1(115.71,80.6) 115.74,80.63 117.76,80.63 arc(119.93,81.06) 121.76,82.29 126.91,87.43 arc(127.16,87.6) 127.45,87.66 128.06,87.66 arc(128.16,87.64) 128.24,87.58 128.37,87.45 arc(128.46,87.4) 128.55,87.38 141.76,87.38 arc(142.2,87.46) 142.58,87.72 J25.A19
DB4+: length 1.5
  BOTTOM w0.254: C33.1 40.77,93.4 arc(40.58,93.36) v1(40.43,93.26)
DB4-: length 1.5
  BOTTOM w0.254: C34.1 40.77,94.11 arc(40.58,94.15) v1(40.43,94.26)
DB4_M: length 104.5
  L10_SIG-2 w0.16: v1(144.15,96.9) 144.15,97.11 arc(144.02,97.4) 143.73,97.52 141.81,97.52 arc(141.31,97.42) 140.89,97.14 140.42,96.67 arc(140.34,96.61) 140.23,96.59 140.1,96.59 arc(138.75,96.32) 137.6,95.56 136.09,94.04 arc(135.77,93.83) 135.39,93.76 134.39,93.76 arc(133.99,93.84) 133.65,94.06 arc(133.1,94.43) 132.45,94.56 122.85,94.56 122.85,94.56 121.7,94.56 v1(121.65,94.61)
  BOTTOM w0.254: v1(121.65,94.61) 121.63,94.58 113.86,94.58 arc(112.62,94.33) 111.58,93.63 111.18,93.24 arc(110.68,92.9) 110.09,92.79 47.31,92.79 arc(46.58,92.93) 45.97,93.34 arc(45.11,93.91) 44.1,94.11 C34.2
DB4_P: length 104.5
  L10_SIG-2 w0.16: v1(144.15,95.63) 144.15,95.47 arc(144.01,95.15) 143.69,95.01 141.64,95.01 arc(141.29,95.08) 140.99,95.28 140.44,95.84 arc(140.34,95.9) 140.23,95.92 140.1,95.92 arc(139,95.7) 138.07,95.08 136.56,93.57 arc(136.02,93.21) 135.39,93.08 134.39,93.08 arc(133.73,93.22) 133.17,93.59 arc(132.84,93.81) 132.45,93.89 122.57,93.89 122.57,93.89 121.7,93.89 v1(121.65,93.84)
  BOTTOM w0.254: C33.2 44.1,93.4 arc(44.84,93.26) 45.47,92.84 arc(46.31,92.27) 47.31,92.08 110.09,92.08 arc(110.95,92.25) 111.68,92.73 112.08,93.13 arc(112.9,93.68) 113.86,93.87 121.63,93.87 v1(121.65,93.84)
DB5+: length 1.5
  BOTTOM w0.254: C35.1 40.77,91.4 arc(40.58,91.36) v1(40.43,91.26)
DB5-: length 1.5
  BOTTOM w0.254: C36.1 40.77,92.11 arc(40.58,92.15) v1(40.43,92.26)
DB5_M: length 105.9
  L10_SIG-2 w0.16: v1(112.49,90.58) 112.56,90.58 113.12,91.14 arc(113.65,91.49) 114.27,91.61 115.58,91.61 arc(117.15,91.3) 118.47,90.42 arc(120.05,89.36) 121.9,89 136.51,89 arc(137.25,89.14) 137.88,89.57 138.24,89.93 arc(139.29,90.62) 140.52,90.87 140.64,90.87 arc(140.8,90.9) 140.93,90.99 140.93,90.99 arc(141.15,91.14) 141.4,91.19 143.68,91.19 arc(144.01,91.32) 144.15,91.65 v1(144.15,91.82)
  BOTTOM w0.254: v1(112.49,90.58) 112.49,90.54 111.64,89.69 arc(111.08,89.31) 110.42,89.18 109.37,89.18 arc(109.18,89.22) 109.01,89.33 108.89,89.46 108.54,89.81 arc(108.35,89.94) 108.12,89.98 107.79,89.98 arc(107.52,89.93) 107.28,89.77 106.85,89.34 arc(106.68,89.22) 106.48,89.18 47.04,89.18 arc(46.25,89.34) 45.59,89.78 43.78,91.59 arc(43.2,91.98) C36.2
DB5_P: length 105.9
  L10_SIG-2 w0.16: v1(113.03,90.04) 113.03,90.1 113.59,90.66 arc(113.9,90.87) 114.27,90.94 115.58,90.94 arc(116.89,90.68) 118,89.94 arc(119.79,88.75) 121.9,88.33 122.55,88.33 arc(122.74,88.29) 122.89,88.18 123.04,88.03 123.05,88.03 arc(123.2,87.93) 123.37,87.89 123.56,87.89 arc(123.75,87.93) 123.91,88.04 124.09,88.22 arc(124.2,88.3) 124.34,88.33 125,88.33 arc(125.19,88.29) 125.34,88.18 125.49,88.03 125.5,88.03 arc(125.63,87.94) 125.79,87.91 126.04,87.91 arc(126.21,87.94) 126.36,88.04 126.54,88.22 arc(126.65,88.3) 126.78,88.33 136.51,88.33 arc(137.51,88.52) 138.36,89.09 138.72,89.45 arc(139.55,90.01) 140.52,90.2 140.64,90.2 arc(140.79,90.17) 140.91,90.09 141.03,89.97 arc(141.09,89.93) 141.16,89.92 143.58,89.92 arc(143.98,90.08) 144.15,90.48 v1(144.15,90.55)
  BOTTOM w0.254: v1(113.03,90.04) 113,90.04 112.14,89.19 arc(111.35,88.66) 110.42,88.47 47.04,88.47 arc(45.98,88.68) 45.09,89.28 43.28,91.09 arc(42.93,91.32) C35.2
DB6+: length 1.5
  BOTTOM w0.254: C37.1 39.57,89.91 arc(39.53,90.1) v1(39.42,90.26)
DB6-: length 1.5
  BOTTOM w0.254: C38.1 40.28,89.91 arc(40.32,90.1) v1(40.43,90.26)
DB6_M: length 113.6
  L10_SIG-2 w0.16: v1(145.41,89.28) 145.41,89.11 arc(145.28,88.78) 144.95,88.65 142.59,88.65 arc(142.38,88.6) 142.2,88.49 142.16,88.44 arc(142.04,88.36) 141.89,88.33 141.12,88.33 arc(140.18,88.14) 139.38,87.61 138.15,86.38 arc(137.51,85.95) 136.75,85.8 128.79,85.8 arc(127.36,85.52) 126.15,84.71 124.44,83 arc(124.07,82.75) 123.62,82.66 122.44,82.66 122.44,82.66 arc(122.34,82.66) 122.24,82.65 121.73,82.65 arc(121.73,82.65) 121.72,82.65 119.5,82.65 arc(118.7,82.81) 118.03,83.26 117,84.29 arc(116.37,84.71) 115.63,84.86 113.4,84.86 arc(112.47,84.68) 111.68,84.15 110.89,83.36 v1(110.83,83.36)
  BOTTOM w0.254: v1(110.83,83.36) 110.83,83.32 110.48,82.97 arc(109.62,82.4) 108.61,82.19 107.64,82.19 arc(107.45,82.23) 107.28,82.34 107.16,82.47 107.16,82.47 107.02,82.61 arc(106.8,82.75) 106.54,82.8 arc(106.25,82.75) 106.01,82.58 105.89,82.47 105.89,82.47 105.77,82.34 arc(105.6,82.23) 105.41,82.19 55.26,82.19 arc(55.06,82.23) 54.9,82.34 54.77,82.47 54.77,82.47 54.63,82.61 arc(54.36,82.79) 54.03,82.86 arc(53.67,82.79) 53.37,82.58 53.25,82.47 53.25,82.47 53.05,82.27 arc(52.97,82.21) 52.87,82.19 52.25,82.19 arc(52.05,82.23) 51.89,82.34 51.76,82.47 51.76,82.47 51.63,82.61 arc(51.41,82.75) 51.15,82.8 arc(50.86,82.75) 50.61,82.58 50.5,82.47 50.5,82.47 50.37,82.34 arc(50.21,82.23) 50.01,82.19 49.52,82.19 arc(49.33,82.23) 49.16,82.34 49.04,82.47 49.04,82.47 48.9,82.61 arc(48.64,82.78) 48.33,82.84 arc(47.99,82.77) 47.71,82.58 47.6,82.47 47.6,82.47 47.47,82.34 arc(47.3,82.23) 47.11,82.19 46.36,82.19 arc(45.74,82.32) 45.21,82.67 41.24,86.64 40.68,87.2 arc(40.38,87.64) C38.2
DB6_P: length 113.6
  L10_SIG-2 w0.16: v1(145.41,88.01) 145.41,87.93 arc(145.25,87.54) 144.86,87.38 142.61,87.38 arc(142.42,87.41) 142.26,87.52 arc(142.11,87.62) 141.93,87.66 141.12,87.66 arc(140.44,87.52) 139.85,87.13 138.63,85.91 arc(137.77,85.33) 136.75,85.13 131.35,85.13 arc(131.22,85.11) 131.11,85.03 130.92,84.84 arc(130.73,84.71) 130.5,84.67 130.46,84.67 arc(130.25,84.71) 130.06,84.83 130.06,84.84 129.91,84.99 arc(129.75,85.09) 129.57,85.13 128.79,85.13 arc(127.62,84.9) 126.63,84.24 124.92,82.53 arc(124.32,82.13) 123.62,81.99 122.48,81.99 arc(122.36,81.98) 122.24,81.98 121.73,81.98 arc(121.59,81.95) 121.47,81.87 121.35,81.75 arc(121.11,81.59) 120.82,81.53 arc(120.61,81.58) 120.43,81.69 120.28,81.84 arc(120.12,81.95) 119.94,81.98 119.5,81.98 arc(118.45,82.19) 117.56,82.79 116.52,83.82 arc(116.11,84.09) 115.63,84.19 113.4,84.19 arc(112.73,84.06) 112.16,83.68 111.37,82.89 v1(111.37,82.82)
  BOTTOM w0.254: v1(111.37,82.82) 111.34,82.82 110.99,82.47 arc(109.89,81.74) 108.61,81.48 46.35,81.48 arc(45.46,81.66) 44.71,82.17 40.73,86.14 40.17,86.7 arc(39.73,87.37) C37.2
DB7+: length 1.5
  BOTTOM w0.254: C39.1 37.57,89.91 arc(37.53,90.1) v1(37.42,90.26)
DB7-: length 1.5
  BOTTOM w0.254: C40.1 38.28,89.91 arc(38.32,90.1) v1(38.43,90.26)
DB7_M: length 115.3
  L10_SIG-2 w0.16: v1(117.41,78.26) 117.45,78.21 123.87,78.21 arc(126.49,78.74) 128.71,80.22 129.95,81.46 arc(131.93,82.78) 134.27,83.25 143.1,83.25 arc(143.27,83.28) 143.41,83.38 143.47,83.44 arc(143.61,83.53) 143.78,83.57 144.95,83.57 arc(145.28,83.7) 145.41,84.03 v1(145.41,84.2)
  BOTTOM w0.254: v1(117.41,78.26) 117.38,78.24 115.88,78.24 115.88,78.23 115.67,78.15 115.66,78.11 115.55,78.06 59.44,78.06 arc(59.24,78.1) 59.07,78.22 58.8,78.48 arc(58.52,78.67) 58.18,78.74 58.02,78.74 arc(57.45,78.63) 56.97,78.31 arc(56.7,78.13) 56.39,78.06 55.42,78.06 arc(55.22,78.1) 55.06,78.21 54.81,78.47 arc(54.56,78.63) 54.27,78.69 53.92,78.69 arc(53.63,78.63) 53.38,78.47 53.25,78.34 arc(52.95,78.14) 52.59,78.06 50.01,78.06 arc(49.8,78.11) 49.62,78.23 49.6,78.24 arc(49.22,78.5) 48.76,78.6 arc(48.28,78.5) 47.88,78.23 arc(47.75,78.15) 47.6,78.12 arc(46.56,78.32) 45.67,78.91 39.59,85 arc(38.62,86.45) C40.2
DB7_P: length 115.3
  L10_SIG-2 w0.16: v1(117.41,77.5) 117.45,77.54 123.87,77.54 arc(126.74,78.12) 129.18,79.74 130.42,80.98 arc(132.19,82.16) 134.27,82.58 135.81,82.58 141.59,82.58 143.07,82.58 arc(143.28,82.54) 143.46,82.42 arc(143.59,82.33) 143.75,82.3 144.95,82.3 arc(145.28,82.43) 145.41,82.76 v1(145.41,82.93)
  BOTTOM w0.254: v1(117.41,77.5) 117.38,77.52 116.18,77.52 116.17,77.52 115.97,77.43 115.93,77.45 115.69,77.35 47.72,77.35 arc(47.5,77.36) 47.28,77.38 arc(47.11,77.41) 46.94,77.44 arc(45.99,77.8) 45.17,78.41 39.09,84.49 arc(37.96,86.17) C39.2
DCLKOUT2_N: length 6.7
  BOTTOM w0.254: C135.1 104.27,117.7 R75.1 104.3,117.78 104.3,118.59 arc(104.21,118.79) 104.01,118.88 103.84,118.88 arc(103.63,118.97) 103.54,119.18 103.54,119.34 arc(103.62,119.52) 103.79,119.59 104.02,119.59 arc(104.22,119.67) 104.3,119.87 104.3,120.32 arc(104.26,120.5) 104.16,120.66 103.72,121.09 arc(103.57,121.2) 103.4,121.27 arc(103.34,121.28) 103.27,121.28 102.89,121.28 102.89,121.29 U4.16
DCLKOUT2_P: length 6.7
  BOTTOM w0.254: U4.15 103.68,121.79 arc(103.94,121.73) 104.16,121.59 104.81,120.93 arc(104.96,120.71) 105.01,120.46 105.01,117.78 R74.1 105.04,117.7 C133.1
DCLKOUT6_N: length 3.3
  BOTTOM w0.152: C153.1 R95.1 96.12,118.52 96.38,118.78 96.38,119.61 96.27,119.72 U4.28
DCLKOUT6_P: length 3.3
  BOTTOM w0.152: C151.1 R94.1 96.88,118.52 96.66,118.74 96.66,119.61 96.77,119.72 U4.27
DCLKOUT8_N: length 6
  BOTTOM w0.152: R24.1 93.54,133.64 R57.1 94.39,133.45 95.15,133.45 95.66,132.94 95.66,130.26 95.77,130.15 U4.52
DCLKOUT8_P: length 5.6
  BOTTOM w0.152: U4.51 95.27,130.16 95.38,130.27 95.38,132.83 95.04,133.17 94.39,133.17 R58.1 93.54,132.98 R22.1
DCLKOUT10_N: length 11.3
  TOP w0.254: J24.1 101.58,136.95 arc(101.28,136.22) 100.55,135.92 98.07,135.92 arc(97.57,135.71) 97.36,135.21 97.36,134.73 v1(97.39,134.7)
  BOTTOM w0.254: v1(97.39,134.7) 97.36,134.68 97.36,132.61 C143.2
DCLKOUT10_P: length 11.3
  TOP w0.254: v1(96.62,134.7) 96.65,134.73 96.65,135.21 arc(96.44,135.71) 95.94,135.92 93.46,135.92 arc(92.73,136.22) 92.43,136.95 J23.1
  BOTTOM w0.254: C142.2 96.65,132.61 96.65,134.68 v1(96.62,134.7)
DCLKOUT10N: length 2.6
  BOTTOM w0.254: U4.55 97.27,131.2 R87.1 97.39,131.31 C143.1
DCLKOUT10P: length 2.6
  BOTTOM w0.254: U4.54 96.77,131.17 R86.1 96.62,131.31 C142.1
DDBUS0: length 26.1
  TOP w0.279: U8.48 64.48,65.35 64.5,65.37 64.94,65.37 64.96,65.35 70.49,65.35 72.9,62.94 72.9,59.85 75.54,57.21 78.89,57.21 79.35,57.68 79.35,60.68 78.83,61.21 U11.3
DDBUS1: length 25
  TOP w0.279: U11.4 75.56,60.56 v1(75.33,60.79) ; v1(74.82,59.8) 74.1,59.8 73.82,60.08 73.82,63 69.42,67.39 65.83,67.39 64.03,69.2 62.52,69.2 61.31,67.99 61.31,67.29 61.29,67.27 61.29,66.84 61.31,66.82 U8.52
  BOTTOM w0.279: v1(74.82,59.8) 74.82,60.29 v1(75.33,60.79)
DDBUS2: length 32
  TOP w0.279: v1(61.76,69.39) 60.81,68.43 U8.53 ; v1(78.77,59.91) U11.5
  BOTTOM w0.279: v1(61.76,69.39) 61.94,69.56 66.85,69.56 72.79,63.62 72.79,59.55 75.35,56.99 78.13,56.99 78.77,57.63 v1(78.77,59.91)
DDBUS3: length 26.5
  TOP w0.279: U8.54 60.31,68.76 v1(60.88,69.33) ; U11.6 76.16,59.26 v1(76.11,59.31)
  BOTTOM w0.279: v1(60.88,69.33) 61.73,70.18 67.85,70.18 74.56,63.48 74.56,62.42 76.11,60.87 v1(76.11,59.31)
DDBUS4: length 39.1
  TOP w0.279: 84.57,65.96 84.57,65.93 R225.2 ; 84.57,65.96 84.57,69.84 83.46,70.95 U12.3 ; 84.57,65.96 81.75,63.14 74.67,63.14 67.74,70.07 60.89,70.07 60.67,69.85 60.66,69.85 60.36,69.55 60.36,69.54 59.94,69.12 59.94,68.97 59.9,68.93 59.9,66.27 U8.55
DDBUS5: length 38.1
  TOP w0.279: U12.4 83.09,70.3 83.87,69.52 83.87,66.21 81.57,63.91 75.06,63.91 68.1,70.87 60.59,70.87 58.8,69.09 58.8,67.33 58.78,67.31 58.78,66.88 58.8,66.86 U8.57
DDBUS6: length 32.5
  TOP w0.279: R226.2 80.5,69.72 v1(80.58,69.65) U12.5 ; U8.58 v1(58.3,69.3)
  BOTTOM w0.279: v1(58.3,69.3) 59.81,70.8 68.98,70.8 74.56,65.22 77.48,65.22 80.25,68 80.25,69.32 v1(80.58,69.65)
DDBUS7: length 35.3
  TOP w0.279: U12.6 80.88,69 80.6,68.71 80.6,65.23 79.99,64.62 75.31,64.62 68.32,71.61 59.58,71.61 57.8,69.83 57.8,69.53 57.78,69.51 57.78,69.08 57.8,69.06 U8.59
DEVCLKIN: length 13.1
  TOP w0.279: J18.1 T2.6
DM: length 49.5
  TOP w0.152: R116.2 11.53,49.53 11.53,50.18 12.18,50.82 36.35,50.82 46.51,60.99 51.12,60.99 52.36,62.23 53.61,62.23 53.73,62.35 U8.7
DP: length 49.5
  TOP w0.152: R117.2 11.81,49.55 11.81,50.06 12.3,50.54 12.85,50.54 13.12,50.28 13.57,50.28 13.84,50.54 14.29,50.54 14.56,50.28 15.01,50.28 15.28,50.54 36.46,50.54 46.62,60.71 51.24,60.71 52.48,61.95 53.62,61.95 53.73,61.85 U8.8
EE_ADDR0_RX: length 20.9
  TOP w0.279: U5.1 124.6,66.38 127.75,69.53 130.8,69.53 131.37,68.96 134.48,68.96 134.52,69 134.97,69 135.01,68.96 v1(140.34,68.96)
EE_ADDR1_RX: length 22
  TOP w0.279: v1(139.06,67.69) 138.5,67.12 127.7,67.12 125.24,64.66 120.25,64.66 119.76,65.15 U5.2
EECLK: length 30.3
  TOP w0.279: U9.2 77.67,67.99 77.39,67.71 75.48,67.71 R124.2 75.38,67.27 75.08,66.97 74.13,66.97 68.71,72.4 58.4,72.4 56.3,70.29 56.3,69.66 56.28,69.64 56.28,69.2 56.3,69.18 U8.62
EECS: length 31.5
  TOP w0.279: v1(75.36,69.71) 75.38,69.69 R125.2 75.57,68.79 U9.1 ; U8.63 55.8,66.75 55.82,66.77 55.82,67.2 55.8,67.22 55.8,67.41 55.31,67.9 v1(53.75,67.9)
  BOTTOM w0.279: v1(53.75,67.9) 53.75,69.68 56.3,72.23 72.84,72.23 v1(75.36,69.71)
EEDATA: length 30.1
  TOP w0.279: U9.3 78.32,67.28 R131.1 78.15,67.18 v1(77.5,66.53) ; U8.61 v1(56.8,69.42)
  BOTTOM w0.279: v1(77.5,66.53) 74.4,66.53 69.45,71.47 57.84,71.47 56.8,70.43 v1(56.8,69.42)
FMC_ADC_SCSB: length 92.6
  TOP w0.152: v1(56.01,46.61) SJP6.1
  L10_SIG-2 w0.127: 106.93,60.71 106.43,60.71 104.78,59.05 104.78,56.26 v1(104.01,55.5)
  L10_SIG-2 w0.165: v3(133.99,63.88) 133.86,63.88 133.1,64.64 129.79,64.64 128.14,62.99 116.97,62.99 115.19,61.21 108.97,61.21 108.46,60.71 106.93,60.71
  BOTTOM w0.127: v1(104.01,55.5) 102.68,54.17
  BOTTOM w0.152: 102.68,54.17 98.55,50.04 91.57,50.04 88.65,47.12 77.85,47.12 77.34,46.61 v1(56.01,46.61)
FMC_ADC_SDI: length 106.2
  TOP w0.152: v1(54.05,44.2) 54.05,51.64 SJP5.1
  L10_SIG-2 w0.127: v3(135.25,66.42) 135.38,66.42 136.27,67.31 136.27,68.58 135.51,69.34 130.94,69.34 130.43,69.85 129.67,69.85 129.03,69.22 126.62,69.22 122.17,64.77 112.01,64.77 110.62,63.37 104.78,63.37 102.49,61.09 102.49,58.8 93.13,49.44 93.13,49.36 92.88,49.11 92.8,49.11 92.11,48.43 91.77,48.43 91.53,48.18 91.53,47.81 89.41,45.69 89.41,45.25 87.59,43.43 75.69,43.43 75.18,43.94 54.31,43.94 v1(54.05,44.2)
FMC_DATA: length 132.6
  TOP w0.152: v1(72.01,41.53) 72.01,50.8 SJP8.1
  L10_SIG-2 w0.127: v1(72.01,41.53) 73.15,40.39 73.15,37.59 73.66,37.08 79.25,37.08 80.1,37.93 94.2,37.93 95.18,38.92 98.23,38.92 98.68,39.37 105.54,39.37 107.44,41.27 107.44,52.45 111.89,56.9 114.81,56.9 115.32,56.39 127.13,56.39 128.52,57.78 140.21,57.78 141.48,59.05 141.48,59.44 141.99,59.94 141.99,61.85 142.62,62.48 142.62,63.88 141.99,64.52 138.68,64.52 138.05,65.15 v3(135.25,65.15)
  BOTTOM w0.152: v1(71.12,51.82) 70.61,51.82 68.96,50.16 63.63,50.16 63.12,50.67 53.85,50.67 52.71,51.82 v1(52.58,51.82)
FMC_LMK_SCSB: length 81.6
  TOP w0.152: v1(74.17,43.18) 72.64,44.7 SJP9.1
  L10_SIG-2 w0.127: v3(134.75,68.45) 126.49,68.45 122.3,64.26 112.14,64.26 110.87,62.99 109.73,62.99 108.39,61.66 107.31,61.66 107.25,61.59 106.3,61.59 94.15,49.44 94.06,49.44 93.81,49.2 93.81,49.11 93.58,48.87 93.52,48.93 93.17,48.93 92.93,48.69 92.93,48.34 92.99,48.28 87.63,42.93 77.2,42.93 77.16,42.96 76.92,42.96 76.88,42.93 74.42,42.93 v1(74.17,43.18)
  BOTTOM w0.279: J25.G34 v3(134.75,68.45)
FMC_LMK_SDI: length 90.5
  TOP w0.152: SJP12.1 69.34,47.75 v1(69.34,45.85)
  L04_SIG-1 w0.127: v1(121.92,61.47) 121.92,70.99 131.95,81.03 v1(134.62,81.03)
  BOTTOM w0.127: v1(121.92,61.47) 121.92,60.96 118.62,57.66 113.67,57.66 109.86,53.85 109.86,52.45
  BOTTOM w0.152: 109.86,52.45 108.46,51.05 101.22,51.05 98.68,48.51 98.68,47.62 98.17,47.12 96.9,47.12 96.52,47.5 95,47.5 93.6,46.1 78.87,46.1 78.61,45.85 v1(69.34,45.85)
  BOTTOM w0.279: J25.G24 v1(134.62,81.03)
FMC_LMX_SCSB: length 76.9
  L10_SIG-2 w0.152: v1(74.17,51.69) 74.17,50.29 77.85,46.61 88.65,46.61
  L10_SIG-2 w0.165: v3(135.25,70.23) 135.13,70.23 134.37,70.99 127.64,70.99 121.79,65.15 111.63,65.15 110.36,63.88 101.98,63.88 100.58,62.48 100.58,58.55 90.99,48.95 90.99,48.95 90.62,48.95 90.37,48.7 90.37,48.33 90.37,48.33 88.65,46.61
FMC_LMX_SDI: length 115.2
  BOTTOM w0.102: 128.78,68.33 131.7,68.33 132.08,67.95 132.08,67.44 132.46,67.06 141.86,67.06 142.24,67.44 142.24,78.13 141.88,78.49 137.54,78.49 137.16,78.87 137.16,84.61 136.93,84.84 135.89,84.84 J25.G21
  BOTTOM w0.152: v1(71.12,48.01) 76.33,48.01 79.88,51.56 94.62,51.56 97.03,53.98 97.03,68.2 99.06,70.23 111,70.23 113.79,67.44 126.87,67.44 127.76,68.33 128.78,68.33
FMC_SCL: length 40.1
  TOP w0.279: J28.2 116.47,67.83 116.47,64.41 118.49,62.39 U5.6
  BOTTOM w0.102: 128.67,69.6 139.47,69.6 139.7,69.82 139.7,71.75 140.08,72.14 140.72,72.14 140.97,72.39 140.97,73.41 J25.C30
  BOTTOM w0.279: 128.67,69.6 127.38,69.6 125.98,68.2 119.38,68.2 J28.2
FMC_SCLK: length 119.8
  TOP w0.152: SJP3.1 v1(50.93,42.29) ; SJP7.1 70.1,51.18 v1(70.1,42.29)
  L10_SIG-2 w0.127: v3(133.99,65.15) 134.11,65.15 134.62,64.64 134.62,63.54 134.45,63.37 130.05,63.37 128.91,62.23 117.6,62.23 115.7,60.32 109.98,60.32 109.22,59.56 106.68,59.56 105.41,58.29 105.41,50.93 98.04,43.56 94.87,43.56 92.2,40.89 86.49,40.89 85.6,40 75.31,40 73.98,41.34
  L10_SIG-2 w0.152: 73.98,41.34 73.03,42.29 v1(70.1,42.29)
  BOTTOM w0.152: v1(50.93,42.29) v1(70.1,42.29)
FMC_SDA: length 37.2
  TOP w0.279: U5.5 117.22,62.27 115.57,63.92 J28.1
  BOTTOM w0.102: J25.C31 139.7,72.14 128.65,72.14
  BOTTOM w0.279: 128.65,72.14 118.24,72.14 J28.1
FPGA_JESD_CLK_A_N: length 59
  L04_SIG-1 w0.124: v1(107.72,128.87) 107.95,129.1 108.73,129.1 109.45,128.37 109.45,117.74 113.05,114.14 125.6,114.14 126.5,113.25 126.5,110.19 125.95,109.64 123.71,109.64 122.7,108.63 122.7,106.5 123.6,105.59 129.96,105.59 130.94,106.57 136.61,106.57 136.91,106.27 138.94,106.27 139.06,106.15 v1(139.06,105.79)
FPGA_JESD_CLK_A_P: length 59
  L04_SIG-1 w0.124: v1(139.06,107.06) 139.06,106.7 138.94,106.58 137.03,106.58 136.74,106.87 130.81,106.87 129.83,105.9 123.73,105.9 123,106.62 123,108.5 123.84,109.34 126.08,109.34 126.81,110.07 126.81,113.37 125.73,114.45 113.17,114.45 109.76,117.87 109.76,128.5 108.85,129.41 107.95,129.41 v1(107.72,129.64)
FPGA_JESD_CLK_B_N: length 59
  L04_SIG-1 w0.124: v1(114.23,110.99) 114.51,111.27 115.17,111.27 122.68,103.77 122.7,103.77 122.72,103.75 134.76,103.75 v1(135.25,103.25)
  BOTTOM w0.152: v1(114.23,110.99) 113.93,111.29 113.12,111.29 110.18,114.24 110.18,130.97 108.62,132.53 108.22,132.53 107.79,132.96 107.79,133.37 107.36,133.8 106.95,133.8 106.52,134.23 106.52,134.63 105.16,135.99 101.43,135.99 101.16,135.72 101.16,135.29 R127.2
FPGA_JESD_CLK_B_P: length 59
  L04_SIG-1 w0.124: v1(135.25,104.52) 134.79,104.05 122.84,104.05 115.3,111.6 114.5,111.6 v1(114.23,111.87)
  BOTTOM w0.152: v1(114.23,111.87) 113.92,111.57 113.24,111.57 110.46,114.35 110.46,131.09 105.28,136.27 101.32,136.27 100.88,135.84 100.88,135.29 R126.2
FPGA_JESD_CLK_C_N: length 97.1
  L04_SIG-1 w0.124: v1(144.15,85.47) 144.15,85.83 144.27,85.95 146.73,85.95 147.46,86.68 147.46,109.16 144.6,112.02 133.66,112.02 127.51,118.16 112.3,118.16 110.83,119.64 110.83,129.57 107.32,133.08 99.74,133.08 99.36,133.46 93.1,133.46 v1(92.88,133.69)
FPGA_JESD_CLK_C_P: length 97.1
  L04_SIG-1 w0.124: v1(92.88,132.93) 93.1,133.16 94.32,133.16 94.55,132.93 95.13,132.93 95.35,133.16 95.93,133.16 96.16,132.93 96.74,132.93 96.97,133.16 97.55,133.16 97.78,132.93 98.36,132.93 98.58,133.16 99.24,133.16 99.61,132.78 107.19,132.78 110.52,129.45 110.52,119.51 112.17,117.86 127.39,117.86 133.53,111.71 144.47,111.71 147.15,109.03 147.15,90.08 146.89,89.81 146.89,89.23 147.15,88.96 147.15,88.38 146.89,88.12 146.89,87.54 147.15,87.27 147.15,86.8 146.61,86.26 144.27,86.26 144.15,86.38 v1(144.15,86.74)
FPGA_JESD_SYSREFM: length 59
  L10_SIG-2 w0.14: v1(107.72,126.38) 107.95,126.61 108.49,126.61 109.58,125.52 109.58,116.2 104.75,111.37 104.75,106.06 110.05,100.76 113.85,100.76 115.92,102.84 128.19,102.84 131.1,99.92 135.12,99.92 135.25,99.78 v1(135.25,99.44)
FPGA_JESD_SYSREFP: length 59
  L10_SIG-2 w0.14: v1(135.25,100.71) 135.25,100.37 135.12,100.23 131.23,100.23 128.31,103.14 115.8,103.14 113.72,101.06 110.17,101.06 105.05,106.18 105.05,111.24 109.89,116.08 109.89,125.64 108.61,126.92 107.95,126.92 v1(107.72,127.15)
GTXCLKM: length 5.1
  BOTTOM w0.152: R129.1 107.06,128.92 R64.1 106.07,128.92 105.88,129.12 105.22,129.12 104.5,128.4 103.23,128.4 103.12,128.29 U4.2
GTXCLKP: length 5.1
  BOTTOM w0.152: R128.1 107.06,129.59 R65.1 106.07,129.59 105.88,129.39 105.1,129.39 104.39,128.68 103.23,128.68 103.12,128.79 U4.1
HSPC_PRSNT_M2C_L: length 23.1
  TOP w0.279: v1(144.15,110.87) 144.15,111.99 141.05,115.08 127.21,115.08 126.21,116.08 J30.1
INA+: length 2.7
  TOP w0.279: BALUN1.3 30.4,109.95 arc(30.52,109.35) 30.86,108.84 31.07,108.63 arc(31.33,108.24) R1.1
INA-: length 2.7
  TOP w0.279: BALUN1.2 33.45,109.95 arc(33.33,109.35) 32.99,108.84 32.78,108.63 arc(32.52,108.24) R4.1
INA_+: length 10.1
  TOP w0.279: R180.1 30.31,107.16 arc(28.11,107.6) 26.26,108.84 25.07,110.02 arc(24.13,111.44) J1.1
INA_-: length 10.1
  TOP w0.279: R179.1 33.54,107.16 arc(35.74,107.6) 37.59,108.84 38.78,110.02 arc(39.72,111.44) J3.1
INAN: length 4.9
  TOP w0.279: R179.2 U1.A5
INAP: length 4.9
  TOP w0.279: R180.2 U1.A4
INB+: length 2.7
  TOP w0.279: BALUN2.2 30.4,81.31 30.4,81.57 arc(30.52,82.17) 30.86,82.68 31.07,82.89 arc(31.33,83.28) R6.1
INB-: length 2.7
  TOP w0.279: BALUN2.3 33.45,81.57 arc(33.33,82.17) 32.99,82.68 32.78,82.89 arc(32.52,83.28) R9.1
INB_+: length 10.1
  TOP w0.279: R151.1 30.31,84.35 arc(28.11,83.92) 26.26,82.68 25.07,81.49 arc(24.13,80.08) J4.1
INB_-: length 10.1
  TOP w0.279: R162.1 33.54,84.35 arc(35.74,83.92) 37.59,82.68 38.78,81.49 arc(39.72,80.08) J6.1
INBN: length 4.9
  TOP w0.279: R9.2 U1.P5
INBP: length 4.9
  TOP w0.254: U1.P4 31.42,84.55 R6.2
JESD_SYSREFM: length 5.2
  BOTTOM w0.152: U4.4 103.12,127.29 103.23,127.4 104.6,127.4 105.37,126.63 105.88,126.63 106.07,126.44 R61.1 107.06,126.44 R60.1
